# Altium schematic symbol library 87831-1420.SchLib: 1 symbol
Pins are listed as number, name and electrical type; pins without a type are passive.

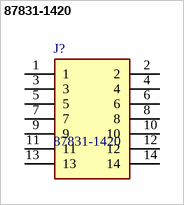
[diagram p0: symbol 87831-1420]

## 87831-1420
designator J?
Header 2.00mm Milli-Grid, vert, TH, 14w Molex MILLI-GRID Series, Series Number 87831, 2mm Pitch 14 Way 2 Row Straight PCB Header, Solder Termination, 2A; Geometry.Height: 6.4mm
footprint SHDR14W55P200_2X7_1665X630X640P
pins: 1, 2, 3, 4, 5, 6, 7, 8, 9, 10, 11, 12, 13, 14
